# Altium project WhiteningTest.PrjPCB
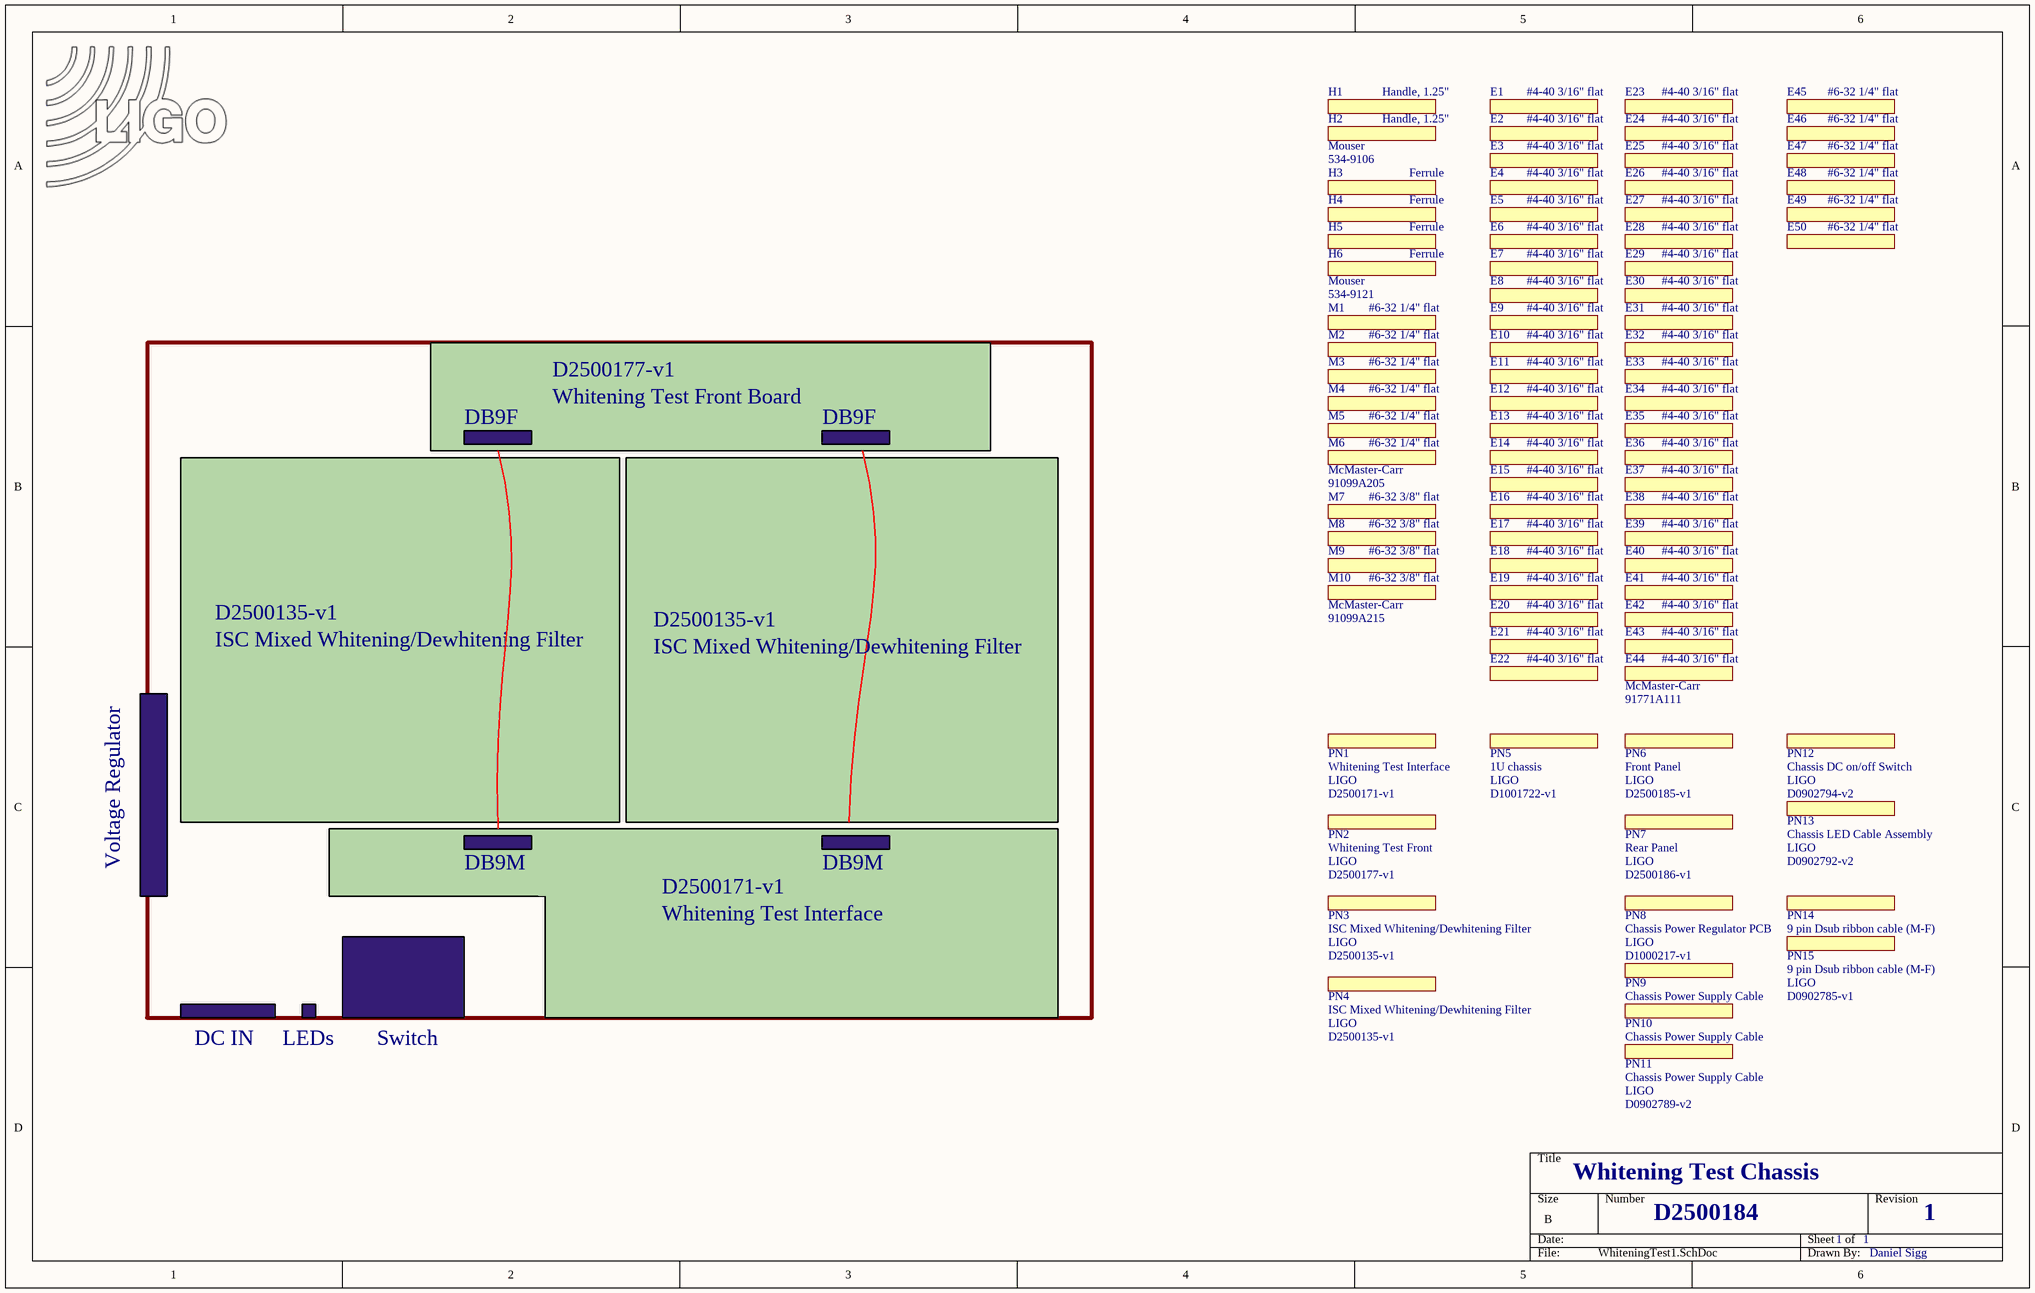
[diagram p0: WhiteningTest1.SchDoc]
REV: 1; DCC: D2500184
1 sheet, 82 parts. Net scope: global (net labels, ports and power ports of the same name join across sheets).

## Sheet WhiteningTest1.SchDoc: DAC Multiplexer
size B; Engineer: Daniel Sigg; DocumentNumber: D2500184; Revision: 1; SheetNumber: 1; SheetTotal: 1; PageSetup: Record=PageOptions¦CenterHorizontal=True¦CenterVertical=True¦PrintScale=1.12¦XCorrection=1.00¦YCorrection=1.00¦PrintKind=0¦BorderSize=5000000¦LeftOffset=0¦BottomOffset=0¦Orientation=2¦PaperLength=1000¦PaperWidth=1000¦Scale=100¦PaperSource=7¦PrintQuality=-4¦MediaType=1¦DitherType=10¦PaperKind=11 x 17¦PrintScaleMode=1

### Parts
E1  #4-40 3/16" flat  (mechanical)
E2  #4-40 3/16" flat  (mechanical)
E3  #4-40 3/16" flat  (mechanical)
E4  #4-40 3/16" flat  (mechanical)
E5  #4-40 3/16" flat  (mechanical)
E6  #4-40 3/16" flat  (mechanical)
E7  #4-40 3/16" flat  (mechanical)
E8  #4-40 3/16" flat  (mechanical)
E9  #4-40 3/16" flat  (mechanical)
E10  #4-40 3/16" flat  (mechanical)
E11  #4-40 3/16" flat  (mechanical)
E12  #4-40 3/16" flat  (mechanical)
E13  #4-40 3/16" flat  (mechanical)
E14  #4-40 3/16" flat  (mechanical)
E15  #4-40 3/16" flat  (mechanical)
E16  #4-40 3/16" flat  (mechanical)
E17  #4-40 3/16" flat  (mechanical)
E18  #4-40 3/16" flat  (mechanical)
E19  #4-40 3/16" flat  (mechanical)
E20  #4-40 3/16" flat  (mechanical)
E21  #4-40 3/16" flat  (mechanical)
E22  #4-40 3/16" flat  (mechanical)
E23  #4-40 3/16" flat  (mechanical)
E24  #4-40 3/16" flat  (mechanical)
E25  #4-40 3/16" flat  (mechanical)
E26  #4-40 3/16" flat  (mechanical)
E27  #4-40 3/16" flat  (mechanical)
E28  #4-40 3/16" flat  (mechanical)
E29  #4-40 3/16" flat  (mechanical)
E30  #4-40 3/16" flat  (mechanical)
E31  #4-40 3/16" flat  (mechanical)
E32  #4-40 3/16" flat  (mechanical)
E33  #4-40 3/16" flat  (mechanical)
E34  #4-40 3/16" flat  (mechanical)
E35  #4-40 3/16" flat  (mechanical)
E36  #4-40 3/16" flat  (mechanical)
E37  #4-40 3/16" flat  (mechanical)
E38  #4-40 3/16" flat  (mechanical)
E39  #4-40 3/16" flat  (mechanical)
E40  #4-40 3/16" flat  (mechanical)
E41  #4-40 3/16" flat  (mechanical)
E42  #4-40 3/16" flat  (mechanical)
E43  #4-40 3/16" flat  (mechanical)
E44  #4-40 3/16" flat  Part Number: 91771A111  Distributor: McMaster-Carr  (mechanical)
E45  #6-32 1/4" flat  (mechanical)
E46  #6-32 1/4" flat  (mechanical)
E47  #6-32 1/4" flat  (mechanical)
E48  #6-32 1/4" flat  (mechanical)
E49  #6-32 1/4" flat  (mechanical)
E50  #6-32 1/4" flat  (mechanical)
H1  Handle, 1.25"  (mechanical)
H2  Handle, 1.25"  Part Number: 534-9106  Distributor: Mouser  (mechanical)
H3  Ferrule  (mechanical)
H4  Ferrule  (mechanical)
H5  Ferrule  (mechanical)
H6  Ferrule  Part Number: 534-9121  Distributor: Mouser  (mechanical)
LOGO1  LIGO logo  [LIGO_LOGO]  (value not drawn)  (no BOM)
M1  #6-32 1/4" flat  (mechanical)
M2  #6-32 1/4" flat  (mechanical)
M3  #6-32 1/4" flat  (mechanical)
M4  #6-32 1/4" flat  (mechanical)
M5  #6-32 1/4" flat  (mechanical)
M6  #6-32 1/4" flat  Part Number: 91099A205  Distributor: McMaster-Carr  (mechanical)
M7  #6-32 3/8" flat  (mechanical)
M8  #6-32 3/8" flat  (mechanical)
M9  #6-32 3/8" flat  (mechanical)
M10  #6-32 3/8" flat  Part Number: 91099A215  Distributor: McMaster-Carr  (mechanical)
PN1  Whitening Test Interface  Part Number: D2500171-v1  Distributor: LIGO  (mechanical)
PN2  Whitening Test Front  Part Number: D2500177-v1  Distributor: LIGO  (mechanical)
PN3  ISC Mixed Whitening/Dewhitening Filter  Part Number: D2500135-v1  Distributor: LIGO  (mechanical)
PN4  ISC Mixed Whitening/Dewhitening Filter  Part Number: D2500135-v1  Distributor: LIGO  (mechanical)
PN5  1U chassis  Part Number: D1001722-v1  Distributor: LIGO  (mechanical)
PN6  Front Panel  Part Number: D2500185-v1  Distributor: LIGO  (mechanical)
PN7  Rear Panel  Part Number: D2500186-v1  Distributor: LIGO  (mechanical)
PN8  Chassis Power Regulator PCB  Part Number: D1000217-v1  Distributor: LIGO  (mechanical)
PN9  Chassis Power Supply Cable  (mechanical)
PN10  Chassis Power Supply Cable  (mechanical)
PN11  Chassis Power Supply Cable  Part Number: D0902789-v2  Distributor: LIGO  (mechanical)
PN12  Chassis DC on/off Switch  Part Number: D0902794-v2  Distributor: LIGO  (mechanical)
PN13  Chassis LED Cable Assembly  Part Number: D0902792-v2  Distributor: LIGO  (mechanical)
PN14  9 pin Dsub ribbon cable (M-F)  (mechanical)
PN15  9 pin Dsub ribbon cable (M-F)  Part Number: D0902785-v1  Distributor: LIGO  (mechanical)

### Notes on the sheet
- DB9F
- Whitening Test Front Board
- D2500177-v1
- D2500135-v1
- ISC Mixed Whitening/Dewhitening Filter
- Voltage Regulator
- DB9M
- D2500171-v1
- Whitening Test Interface
- DC IN
- LEDs
- Switch
- Whitening Test Chassis
- 1
- Daniel Sigg

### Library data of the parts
E1-E43 = Partlist: #4-40 3/16" flat head screw; Part Number: 91771A111
E44 = Partlist: #4-40 3/16" flat head screw
E45-E50 M1-M5 = Partlist: #6-32 1/4" flat head screw; Part Number: 91099A205
H1 = Partlist: Rack handle; Part Number: 534-9106
H2 = Partlist: Rack handle
H3-H5 = Partlist: Part Number: 534-9121
H6 = Partlist
LOGO1 = LIGO_logo
M6 = Partlist: #6-32 1/4" flat head screw
M7-M9 = Partlist: #6-32 3/8" flat head screw; Part Number: 91099A215
M10 = Partlist: #6-32 3/8" flat head screw
PN1-PN4 PN8 = Partlist: PCB
PN5 = Partlist: chassis
PN6 PN7 = Partlist: panel
PN9 PN10 = Partlist: cable; Part Number: D0902789-v2
PN11 PN15 = Partlist: cable
PN12 = Partlist: chassis switch
PN13 = Partlist: chassis LED
PN14 = Partlist: cable; Part Number: D0902785-v1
